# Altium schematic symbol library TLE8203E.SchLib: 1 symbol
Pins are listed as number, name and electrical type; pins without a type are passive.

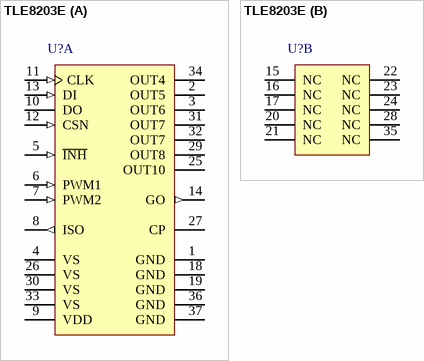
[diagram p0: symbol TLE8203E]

## TLE8203E
designator U?
Mirror Power IC, -40 to 150 degC, PG-DSO-36-50, Reel, Green; Manufacturer: Infineon; PartNumber: TLE8203E; Green: TRUE; Group: Door Module IC´s; IPeak: 6.25 A for OUT 7; Iq: Icc_q = 1 uA max ; Is_q = 5 uA max; Iq (typ): 0.2 uA; 2.5 uA; Operating Range: 8 to 20 V; 5 to 40 V; Protect: OT, OV, OL, SC
footprint INF-PG-DSO-36-50_N (SOP, 36-Leads, Body 12.7x7.5mm, Pitch 0.65mm, Thermal Pad 6000x5400mm, IPC Medium Density)
footprint INF-PG-DSO-36-50_L (SOP, 36-Leads, Body 12.7x7.5mm, Pitch 0.65mm, Thermal Pad 6000x5400mm, IPC High Density)
footprint INF-PG-DSO-36-50_M (SOP, 36-Leads, Body 12.7x7.5mm, Pitch 0.65mm, Thermal Pad 6000x5400mm, IPC Low Density)
part A pins: 1 GND (power) "Ground; internally connected to cooling tab (heat slug).", 2 OUT5 (power) "Power-Output of half-bridge 5; DMOS half-bridge", 3 OUT6 (power) "Power-Output of half-bridge 6; DMOS half-bridge.", 4 VS (power) "Power supply; needs decoupling capacitors to GND. > 47uF electrolytic in parallel with 100nF ceramic is recommended. All Vs pins must be connected externally", 5 ~{INH} (in) "Inhibit; active low. Sets the device in sleep mode with low current consumption when left open or pulled to LOW. Has an internal pull down current source", 6 PWM1 (in) "Logic Input for direct power stage control; direct input to control the high-side switches selected by the SPI xsel1 bits in control register CtrlReg01", 7 PWM2 (in) "Logic Input for direct power stage control; direct input to control the switches selected by the SPI xsel2 bits in control register CtrlReg11", 8 ISO (out) "Current sense output; Mirrors the current of the high-side switch selected by the current sense multiplexer control bits ISx", 9 VDD (power) "Logic Supply Voltage; needs decoupling capacitors to GND (pin 1). 10 uF electrolytic in parallel with 10 nF ceramic is recommended.", 10 DO (hiz) "Serial Data Output; Transfers data to the master when the chip is selected by CSN=LOW. Data transmission is synchronized by CLK, DO state is changed on the rising edge of CLK. The most significant bit (MSB) is transferred (See Datasheet)", 11 CLK (in) "Serial Data Clock Input; Receives the clock signal from the master and clocks the SPI shift register. Has an internal pull down current source", 12 CSN (in) "Serial Port Chip Select Not Input; SPI communication is enabled by pulling CSN to LOW. CLK must be LOW during the transition of CSN. The CSN-pin has an internal pull-up current source", 13 DI (in) "Serial Data Input; Receives serial data from the master when the chip is selected by CSN=LOW. Data transmission is synchronized by CLK. Data are accepted on the falling edge of CLK. The LSB is transferred first. The DI-pin (See Datasheet)", 14 GO (out) "Gate Out; Charge pump output to drive the gate of external n-channel MOS-FET for reverse polarity protection", 18 GND (power) "Ground; internally connected to cooling tab (heat slug).", 19 GND (power) "Ground; internally connected to cooling tab (heat slug).", 25 OUT10 (power) "Power-Output of High-Side Switch output 10; DMOS high-side switch (lamp driver", 26 VS (power) "Power supply; needs decoupling capacitors to GND. > 47uF electrolytic in parallel with 100nF ceramic is recommended. All Vs pins must be connected externally", 27 CP "Charge Pump; pin for optional external charge-pump reservoir capacitor. 3.3 nF to Vs is recommended", 29 OUT8 (power) "Power-Output of High-Side Switch output 8; DMOS high-side switch (lamp driver)", 30 VS (power) "Power supply; needs decoupling capacitors to GND. > 47uF electrolytic in parallel with 100nF ceramic is recommended. All Vs pins must be connected externally", 31 OUT7 (power) "Power Output of High-Side Switch output 7; DMOS high-side switch (mirror heat)", 32 OUT7 (power) "Power Output of High-Side Switch output 7; DMOS high-side switch (mirror heat)", 33 VS (power) "Power supply; needs decoupling capacitors to GND. > 47uF electrolytic in parallel with 100nF ceramic is recommended. All Vs pins must be connected externally", 34 OUT4 (power) "Power-Output of Half-Bridge output 4; DMOS half-bridge (sum of mirror position).", 36 GND (power) "Ground; internally connected to cooling tab (heat slug).", 37 GND (power) "Cooling Tab; internally connected to GND; To reduce thermal resistance, place cooling areas and thermal vias on PCB."
part B pins: 15 NC "Not Connected", 16 NC "Not Connected", 17 NC "Not Connected", 20 NC "Not Connected", 21 NC "Not Connected", 22 NC "Not Connected", 23 NC "Not Connected", 24 NC "Not Connected", 28 NC "Not Connected", 35 NC "Not connected"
